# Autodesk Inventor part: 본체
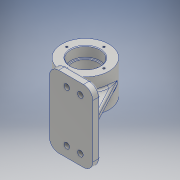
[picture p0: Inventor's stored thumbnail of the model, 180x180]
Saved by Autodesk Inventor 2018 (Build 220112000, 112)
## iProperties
Created: 2023-08
Part Number: 본체
Material: 알루미늄 6061
Document SubType Name: Modeling
Designer: home
Density: 2.7 g/cm^3
Appearance: 알루미늄 - 평지
Mass: 777.806 g
Surface Area: 536.474 cm^2
Volume: 288.076 cm^3
Author: home
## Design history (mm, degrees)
sketch "스케치1"
  geometry: L1 (35, -58)-(-35, -58); L2 (-35, -58)-(-35, 58); L3 (-35, 58)-(35, 58); L4 (35, 58)-(35, -58); 3 further points
  constraints: 8 end point, 2 midpoint, 2 parallel, 1 horizontal, 1 horizontal alignment, 1 perpendicular, 1 vertical alignment
  dimensions: "d0" = 70 distance of L1.start L1.end; "d1" = 116 distance of L1.end L2.end
extrude "돌출1" new body sketch "스케치1" distance "d2" = 12; taper "d3" = 0 deg
sketch "스케치2"
  geometry: L1 (-7, 41)-(15, 41); L2 (-7, 31)-(15, 31); L3 (15, 51)-(-7, 51); L4 (35, -58)-(35, 58) reference; A1 r 10 centre (-7, 41) between (-7, 51) and (-7, 31); A2 r 10 centre (15, 41) between (15, 31) and (15, 51); 2 further points
  constraints: 8 end point, 4 point on circle, 4 tangent, 2 centre point, 1 horizontal, 1 midpoint, 1 parallel
  dimensions: "d4" = 10 radius of A2; "d5" = 22 distance of L2.start L2.end; "d6" = 41 vertical distance of point (4, 41) point (0, 0); "d8" = 20 distance from line of L4 L1.end
extrude "돌출2" join sketch "스케치2" distance "d9" = 3; taper "d10" = 0 deg
sketch "스케치3"
  geometry: C1 r 4.5 at (-7, 41); C2 r 4.5 at (15, 41); A1 r 10 centre (15, 41) between (15, 31) and (15, 51) reference; A2 r 10 centre (-7, 41) between (-7, 51) and (-7, 31) reference; 1 further point
  constraints: 2 centre point, 2 coincident, 1 equal radius
  dimensions: "d11" = 9 diameter of C2
extrude "돌출3" cut sketch "스케치3" extent not by distance; stored distance "d12" = 0; taper "d13" = 0 deg
fillet "모깎기1" dims "d14" = 3
node "작업 평면1"
sketch "스케치4"
  geometry: L1 (6.062, 70)-(109.938, 70); L2 (31, 70)-(31, 108); L3 (31, 108)-(85, 108); L4 (85, 108)-(85, 70); L5 (31, 70)-(85, 70); 3 further points
  constraints: 10 end point, 3 midpoint, 2 perpendicular, 2 point on line, 2 vertical alignment, 1 collinear, 1 horizontal, 1 vertical
  dimensions: "d16" = 70 distance of point (58, 0) point (58, 70); "d17" = 76 diameter of L3 L1; "d18" = 54 distance of L2.end L3.end
revolve "회전1" sketch "스케치4" stored, may be unused: angle "d19" = 90 deg
sketch "스케치5"
  geometry: C1 r 38 at (0, 0) reference; C2 r 20.5 at (0, 0); 1 further point
  constraints: 1 centre point, 1 coincident
  dimensions: "d20" = 41 diameter of C2
extrude "돌출4" cut sketch "스케치5" extent not by distance; stored distance "d21" = 3; taper "d22" = 0 deg
sketch "스케치6"
  geometry: C1 r 20.5 at (0, 0) reference; C2 r 38 at (0, 0) reference; C3 r 23.5 at (0, 0); 1 further point
  constraints: 1 centre point, 1 coincident
  dimensions: "d23" = 47 diameter of C3
extrude "돌출5" cut sketch "스케치6" distance "d24" = 17; taper "d25" = 0 deg
node "작업 평면2"
sketch "스케치7"
  geometry: L1 (-85, 27)-(-9, 27) reference; L2 (-85, -27)-(-9, -27) reference; C1 r 8 at (-47, 0); 2 further points
  constraints: 1 centre point, 1 horizontal alignment, 1 midpoint, 1 vertical alignment
  dimensions: "d27" = 16 diameter of C1
extrude "돌출6" join sketch "스케치7" stored distance "d28" = 17; taper "d29" = 0 deg
sketch "스케치8"
  geometry: C1 r 8 at (0, 0) reference; C2 r 3.5 at (0, 0); 1 further point
  constraints: 1 centre point, 1 coincident
  dimensions: "d30" = 7 diameter of C2
extrude "돌출7" cut sketch "스케치8" distance "d31" = 4; taper "d32" = 0 deg
sketch "스케치9"
  geometry: C1 r 3.5 at (0, 0) reference; 1 further point
hole "구멍1" sketch "스케치9" at (0, 0) diameter "d33" = 5.188; stored, may be unused: countersink angle "d37" = 90 deg, drill point angle "d39" = 118 deg; dims "d34" = 20, "d35" = 4, "d36" = 2, "d38" = 20
chamfer "모따기1" distance "d40" = 1; stored, may be unused: second distance "d41" = 2, angle "d42" = 45 deg
fillet "모깎기2" dims "d43" = 1
sketch "스케치10"
  geometry: L1 (0, 0)-(30, 0); C1 r 38 at (0, 0) reference; 1 further point
  constraints: 2 end point, 1 horizontal
  dimensions: "d44" = 30 distance of L1.start L1.end
hole "구멍2" sketch "스케치10" at (30, 0) diameter "d45" = 3.242; stored, may be unused: countersink angle "d49" = 90 deg, drill point angle "d51" = 118 deg; dims "d46" = 8, "d47" = 4, "d48" = 2, "d50" = 10
fillet "모깎기3" dims "d55" = 3
sketch "스케치11"
  geometry: L1 (31, 108)-(31, 32) reference; L2 (39.534, 39)-(76.466, 39); L3 (85, 108)-(85, 32) reference; L4 (116, 12)-(0, 12) reference; L5 (22, 12)-(39.534, 39); L6 (76.466, 39)-(94, 12); L7 (0, 0)-(0, 12) reference; L8 (116, 0)-(116, 12) reference; 1 further point
  constraints: 6 end point, 2 point on line, 1 horizontal
  dimensions: "d56" = 33 deg angle of L7 L5; "d57" = 33 deg angle of L8 L6; "d58" = 22 distance from line of L7 L5.start; "d59" = 22 distance from line of L8 L6.end; "d60" = 27 distance between parallel lines of L4 L2
feature "리브1" sketch "스케치11" dims "d61" = 1, "d62" = 8, "d63" = 0, "d64" = 0, "d65" = 1, "d66" = 1
sketch "스케치12"
  geometry: L1 (-13.471, 87.882)-(27, 12); L2 (35, 12)-(-35, 12) reference; L3 (35, 0)-(35, 12) reference; L4 (-35, 12)-(-27, 12) reference; L5 (27, 12)-(-35, 12); 2 further points
  constraints: 4 end point, 1 horizontal, 1 point on line, 3 other
  dimensions: "d67" = 8 distance from line of L3 L1.end
feature "리브2" sketch "스케치12" dims "d68" = 1, "d69" = 12, "d70" = 0, "d71" = 0, "d72" = 1, "d73" = 1
fillet "모깎기4" dims "d74" = 15
fillet "모깎기5" dims "d75" = 3
fillet "모깎기6" dims "d76" = 3
fillet "모깎기7" dims "d77" = 3
fillet "모깎기8" dims "d78" = 3
sketch "스케치13"
  geometry: L1 (26.979, 25.778)-(59.021, 25.778); L2 (59.021, 25.778)-(59.021, 12.222); L3 (59.021, 12.222)-(26.979, 12.222); L4 (26.979, 12.222)-(26.979, 25.778); L5 (86, 0)-(0, 0) reference; 4 further points
  constraints: 3 midpoint, 1 vertical alignment, 2 other
  dimensions: "d79" = 19 distance from line of L5 point (26.979, 19)
feature "엠보싱1" sketch "스케치13" dims "d0" = 70, "d1" = 116, "d80" = 0.5, "d81" = 0
fillet "모깎기9" dims "d82" = 3
node "솔리드1"
mirror "미러1"
mirror "미러2"
pattern_circular "원형 패턴1" dims angle "d53" = 360 deg
mirror "미러3"
node "투영된 루프1"
node "투영된 루프2"
node "투영된 루프3"
node "투영된 루프4"
other parameters: "d15" = -82, "d26" = -111
